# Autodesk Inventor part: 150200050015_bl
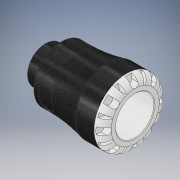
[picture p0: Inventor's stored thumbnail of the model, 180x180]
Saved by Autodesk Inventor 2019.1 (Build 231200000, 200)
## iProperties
Created: 2016-12
Part Number: 150200050015_bl
Material: PVC-Piping
Description: PLASSON G-PLASS Male Adaptor 50X 1 1/2''
Document SubType Name: Modeling
Designer: KIM
Mass: 61.7504 g
Surface Area: 140.097 cm^2
Volume: 44.1074 cm^3
Density: 1.4 g/cm^3
Appearance: Black Cast
Author: KIM
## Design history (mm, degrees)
derived "150200.ipt"
feature "Solid1::150200.ipt" dims "ScaleForDerivedMember" = 10
tag "TaggingFeature1"
body "Solid1"
other parameters: "d0" = 118 [user parameter], "d1" = 35.7 [user parameter], "d3" = 62.5 [user parameter], "d4" = 85 [user parameter], "d6" = 85 [user parameter], "d8" = 72.25 [user parameter], "d13" = 9 [user parameter], "d14" = 9 [user parameter], "d15" = 0 [user parameter], "d17" = 360 deg [user parameter], "d19" = 8 deg [user parameter], "d20" = 1 [user parameter], "d21" = 1 [user parameter], "d22" = 8 deg [user parameter], "d24" = 0 [user parameter], "d26" = 360 deg [user parameter], "d32" = 0.925 [user parameter], "d33" = 8.5 [user parameter], "d34" = 47.803 [user parameter], "d35" = 6.25 [user parameter], "d38" = 21 [user parameter], "d39" = 1.43409 [user parameter], "d42" = 17.5 [user parameter], "d43" = 11.5 [user parameter], "d45" = 17.64 [user parameter], "d46" = 0 [user parameter], "d59" = 360 deg [user parameter], "d61" = 14.875 [user parameter], "d62" = 1 [user parameter], "d64" = 0 [user parameter], "d65" = 0.85 [user parameter], "E_" = 85 [user parameter], "H_" = 118 [user parameter], "l_" = 85 [user parameter], "R_" = 47.803 [user parameter], "l_2" = 21 [user parameter], "d9" = 11.25 [user parameter], "d11" = 85 [user parameter], "d12" = 62.5 [user parameter]
